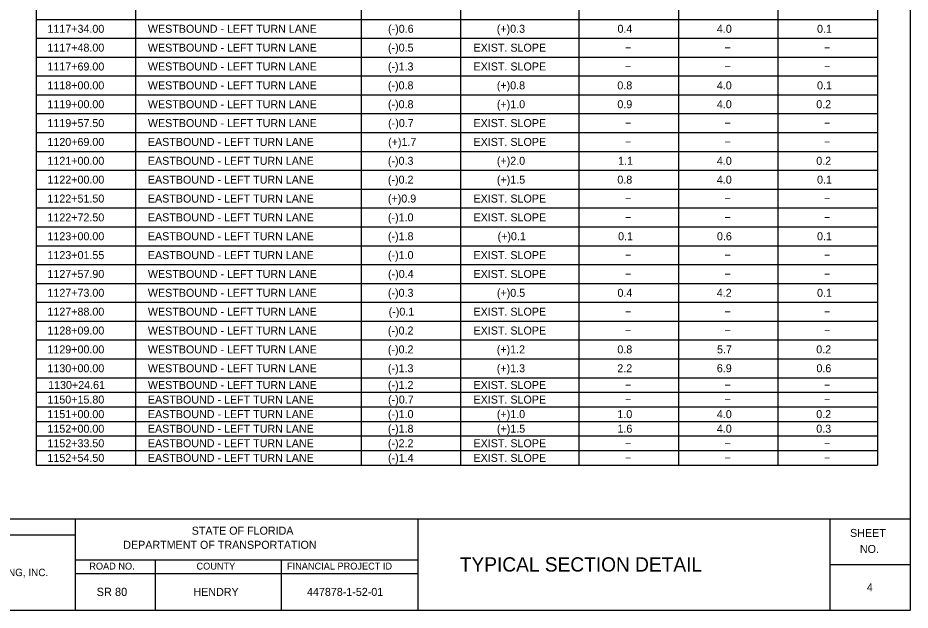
# Model space of a CAD drawing. Extents: x 0.03 to 1.66, y 0 to 0.87.
# Drawn here: x 0.679 to 1.329, y 0.004 to 0.436 of the extents above; entities that cross this region are included whole.
import ezdxf

# ---------------------------------------------------------------- set-up
doc = ezdxf.new("R2010")
doc.units = 0
for name, color, linetype in [('SheetBorder_dp', 7, 'Continuous'), ('SheetLines_dp', 7, 'Continuous'), ('SumBoxBorder_dp', 7, 'Continuous'), ('SumBoxLines_dp', 7, 'Continuous'), ('SumBoxLinesMin_dp', 7, 'Continuous'), ('TextLabel', 7, 'Continuous'), ('TextMisc', 7, 'Continuous'), ('TextShtNo', 7, 'Continuous')]:
    doc.layers.add(name, color=color, linetype=linetype)

msp = doc.modelspace()

# ---------------------------------------------------------------- linework, layer by layer
at = {"layer": 'SheetBorder_dp'}
for p, q in [((1.32916, 0.87083), (1.32916, 0.00417)), ((0.04583, 0.07083), (1.32916, 0.07083)), ((0.04583, 0.00417), (1.32916, 0.00417))]:
    msp.add_line(p, q, dxfattribs=at)
at = {"layer": 'SheetLines_dp'}
for p, q in [((0.72083, 0.07083), (0.72083, 0.00417)), ((0.97083, 0.00417), (0.97083, 0.07083)), ((1.27083, 0.00417), (1.27083, 0.07083)), ((0.52621, 0.05917), (0.72084, 0.05917)), ((0.72083, 0.04083), (0.97083, 0.04083)), ((0.77916, 0.04083), (0.77916, 0.00417)), ((0.87083, 0.04083), (0.87083, 0.00417)), ((1.27083, 0.0375), (1.32916, 0.0375)), ((0.72083, 0.03083), (0.97083, 0.03083))]:
    msp.add_line(p, q, dxfattribs=at)
at = {"layer": 'SumBoxBorder_dp'}
msp.add_line((1.30527, 0.82332), (1.30527, 0.10985), dxfattribs=at)
msp.add_line((1.30527, 0.82332), (1.30527, 0.10985), dxfattribs=at)
at = {"layer": 'SumBoxLines_dp'}
for p, q in [((0.69239, 0.82332), (0.69239, 0.10985)), ((0.92917, 0.80332), (0.92917, 0.10985)), ((0.92917, 0.80332), (0.92917, 0.10985)), ((1.00164, 0.80332), (1.00164, 0.10985)), ((1.00164, 0.80332), (1.00164, 0.10985)), ((1.08785, 0.80332), (1.08785, 0.10985)), ((1.08785, 0.80332), (1.08785, 0.10985)), ((1.16032, 0.80332), (1.16032, 0.10985)), ((1.16032, 0.80332), (1.16032, 0.10985)), ((1.23279, 0.80332), (1.23279, 0.10985)), ((1.23279, 0.80332), (1.23279, 0.10985)), ((0.76486, 0.78333), (0.76486, 0.10985)), ((0.76486, 0.78333), (0.76486, 0.10985))]:
    msp.add_line(p, q, dxfattribs=at)
at = {"layer": 'SumBoxLinesMin_dp'}
for p, q in [((0.69239, 0.43472), (1.30527, 0.43472)), ((0.69239, 0.43472), (1.30527, 0.43472)), ((0.69239, 0.42098), (1.30527, 0.42098)), ((0.69239, 0.42098), (1.30527, 0.42098)), ((0.69239, 0.40723), (1.30527, 0.40723)), ((0.69239, 0.40723), (1.30527, 0.40723)), ((0.69239, 0.39349), (1.30527, 0.39349)), ((0.69239, 0.39349), (1.30527, 0.39349)), ((0.69239, 0.37974), (1.30527, 0.37974)), ((0.69239, 0.37974), (1.30527, 0.37974)), ((0.69239, 0.366), (1.30527, 0.366)), ((0.69239, 0.366), (1.30527, 0.366)), ((0.69239, 0.35225), (1.30527, 0.35225)), ((0.69239, 0.35225), (1.30527, 0.35225)), ((0.69239, 0.33851), (1.30527, 0.33851)), ((0.69239, 0.33851), (1.30527, 0.33851)), ((0.69239, 0.32477), (1.30527, 0.32477)), ((0.69239, 0.32477), (1.30527, 0.32477)), ((0.69239, 0.31102), (1.30527, 0.31102)), ((0.69239, 0.31102), (1.30527, 0.31102)), ((0.69239, 0.29728), (1.30527, 0.29728)), ((0.69239, 0.29728), (1.30527, 0.29728)), ((0.69239, 0.28353), (1.30527, 0.28353)), ((0.69239, 0.28353), (1.30527, 0.28353)), ((0.69239, 0.26979), (1.30527, 0.26979)), ((0.69239, 0.26979), (1.30527, 0.26979)), ((0.69239, 0.25604), (1.30527, 0.25604)), ((0.69239, 0.25604), (1.30527, 0.25604)), ((0.69239, 0.2423), (1.30527, 0.2423)), ((0.69239, 0.2423), (1.30527, 0.2423)), ((0.69239, 0.22855), (1.30527, 0.22855)), ((0.69239, 0.22855), (1.30527, 0.22855)), ((0.69239, 0.21481), (1.30527, 0.21481)), ((0.69239, 0.21481), (1.30527, 0.21481)), ((0.69239, 0.20107), (1.30527, 0.20107)), ((0.69239, 0.20107), (1.30527, 0.20107)), ((0.69239, 0.18732), (1.30527, 0.18732)), ((0.69239, 0.18732), (1.30527, 0.18732)), ((0.69239, 0.17358), (1.30527, 0.17358)), ((0.69239, 0.17358), (1.30527, 0.17358)), ((0.69239, 0.16296), (1.30527, 0.16296)), ((0.69239, 0.16296), (1.30527, 0.16296)), ((0.69239, 0.15233), (1.30527, 0.15233)), ((0.69239, 0.15233), (1.30527, 0.15233)), ((0.69239, 0.14171), (1.30527, 0.14171)), ((0.69239, 0.14171), (1.30527, 0.14171)), ((0.69239, 0.13109), (1.30527, 0.13109)), ((0.69239, 0.13109), (1.30527, 0.13109)), ((0.69239, 0.12047), (1.30527, 0.12047)), ((0.69239, 0.12047), (1.30527, 0.12047)), ((0.69239, 0.10985), (1.30527, 0.10985))]:
    msp.add_line(p, q, dxfattribs=at)

# ---------------------------------------------------------------- texts
at = {"layer": 'TextLabel'}
for s, height, p in [('1117+34.00', 0.005831, (0.70065, 0.42493)), ('WESTBOUND - LEFT TURN LANE', 0.005831, (0.77383, 0.42493)), ('(-)0.6', 0.005831, (0.94879, 0.42493)), ('(+)0.3', 0.005831, (1.02802, 0.42493)), ('0.4', 0.005831, (1.11594, 0.42493)), ('4.0', 0.005831, (1.18835, 0.42493)), ('0.1', 0.005831, (1.26133, 0.42493)), ('1117+48.00', 0.005831, (0.70065, 0.41119)), ('WESTBOUND - LEFT TURN LANE', 0.005831, (0.77383, 0.41119)), ('(-)0.5', 0.005831, (0.94875, 0.41119)), ('EXIST. SLOPE', 0.005831, (1.01107, 0.41119)), ('−', 0.00583, (1.12147, 0.41119)), ('−', 0.00583, (1.19394, 0.41119)), ('−', 0.00583, (1.26641, 0.41119)), ('1117+69.00', 0.005831, (0.70065, 0.39745)), ('WESTBOUND - LEFT TURN LANE', 0.005831, (0.77383, 0.39745)), ('(-)1.3', 0.005831, (0.94867, 0.39745)), ('EXIST. SLOPE', 0.005831, (1.01107, 0.39745)), ('−', 0.00583, (1.12147, 0.39745)), ('−', 0.00583, (1.19394, 0.39745)), ('−', 0.00583, (1.26641, 0.39745)), ('1118+00.00', 0.005831, (0.70065, 0.3837)), ('WESTBOUND - LEFT TURN LANE', 0.005831, (0.77383, 0.3837)), ('(-)0.8', 0.005831, (0.9487, 0.3837)), ('(+)0.8', 0.005831, (1.02804, 0.3837)), ('0.8', 0.005831, (1.11585, 0.3837)), ('4.0', 0.005831, (1.18835, 0.3837)), ('0.1', 0.005831, (1.26133, 0.3837)), ('1119+00.00', 0.005831, (0.70065, 0.36996)), ('WESTBOUND - LEFT TURN LANE', 0.005831, (0.77383, 0.36996)), ('(-)0.8', 0.005831, (0.9487, 0.36996)), ('(+)1.0', 0.005831, (1.02807, 0.36996)), ('0.9', 0.005831, (1.11586, 0.36996)), ('4.0', 0.005831, (1.18835, 0.36996)), ('0.2', 0.005831, (1.26077, 0.36996)), ('1119+57.50', 0.005831, (0.70065, 0.35621)), ('WESTBOUND - LEFT TURN LANE', 0.005831, (0.77383, 0.35621)), ('(-)0.7', 0.005831, (0.94884, 0.35621)), ('EXIST. SLOPE', 0.005831, (1.01107, 0.35621)), ('−', 0.00583, (1.12147, 0.35621)), ('−', 0.00583, (1.19394, 0.35621)), ('−', 0.00583, (1.26641, 0.35621)), ('1120+69.00', 0.005831, (0.70065, 0.34247)), ('EASTBOUND - LEFT TURN LANE', 0.005831, (0.77383, 0.34247)), ('(+)1.7', 0.005831, (0.94884, 0.34247)), ('EXIST. SLOPE', 0.005831, (1.01107, 0.34247)), ('−', 0.00583, (1.12147, 0.34247)), ('−', 0.00583, (1.19394, 0.34247)), ('−', 0.00583, (1.26641, 0.34247)), ('1121+00.00', 0.005831, (0.70065, 0.32872)), ('EASTBOUND - LEFT TURN LANE', 0.005831, (0.77383, 0.32872)), ('(-)0.3', 0.005831, (0.94867, 0.32872)), ('(+)2.0', 0.005831, (1.02807, 0.32872)), ('1.1', 0.005831, (1.11639, 0.32872)), ('4.0', 0.005831, (1.18835, 0.32872)), ('0.2', 0.005831, (1.26077, 0.32872)), ('1122+00.00', 0.005831, (0.70065, 0.31498)), ('EASTBOUND - LEFT TURN LANE', 0.005831, (0.77383, 0.31498)), ('(-)0.2', 0.005831, (0.94868, 0.31498)), ('(+)1.5', 0.005831, (1.02809, 0.31498)), ('0.8', 0.005831, (1.11585, 0.31498)), ('4.0', 0.005831, (1.18835, 0.31498)), ('0.1', 0.005831, (1.26133, 0.31498)), ('1122+51.50', 0.005831, (0.70065, 0.30123)), ('EASTBOUND - LEFT TURN LANE', 0.005831, (0.77383, 0.30123)), ('(+)0.9', 0.005831, (0.94871, 0.30123)), ('EXIST. SLOPE', 0.005831, (1.01107, 0.30123)), ('−', 0.00583, (1.12147, 0.30123)), ('−', 0.00583, (1.19394, 0.30123)), ('−', 0.00583, (1.26641, 0.30123)), ('1122+72.50', 0.005831, (0.70065, 0.28749)), ('EASTBOUND - LEFT TURN LANE', 0.005831, (0.77383, 0.28749)), ('(-)1.0', 0.005831, (0.94872, 0.28749)), ('EXIST. SLOPE', 0.005831, (1.01107, 0.28749)), ('−', 0.00583, (1.12147, 0.28749)), ('−', 0.00583, (1.19394, 0.28749)), ('−', 0.00583, (1.26641, 0.28749)), ('1123+00.00', 0.005831, (0.70065, 0.27374)), ('EASTBOUND - LEFT TURN LANE', 0.005831, (0.77383, 0.27374)), ('(-)1.8', 0.005831, (0.9487, 0.27374)), ('(+)0.1', 0.005831, (1.02858, 0.27374)), ('0.1', 0.005831, (1.11639, 0.27374)), ('0.6', 0.005831, (1.18841, 0.27374)), ('0.1', 0.005831, (1.26133, 0.27374)), ('1123+01.55', 0.005831, (0.70068, 0.26)), ('EASTBOUND - LEFT TURN LANE', 0.005831, (0.77383, 0.26)), ('(-)1.0', 0.005831, (0.94872, 0.26)), ('EXIST. SLOPE', 0.005831, (1.01107, 0.26)), ('−', 0.00583, (1.12147, 0.26)), ('−', 0.00583, (1.19394, 0.26)), ('−', 0.00583, (1.26641, 0.26)), ('1127+57.90', 0.005831, (0.70065, 0.24626)), ('WESTBOUND - LEFT TURN LANE', 0.005831, (0.77383, 0.24626)), ('(-)0.4', 0.005831, (0.94879, 0.24626)), ('EXIST. SLOPE', 0.005831, (1.01107, 0.24626)), ('−', 0.00583, (1.12147, 0.24626)), ('−', 0.00583, (1.19394, 0.24626)), ('−', 0.00583, (1.26641, 0.24626)), ('1127+73.00', 0.005831, (0.70065, 0.23251)), ('WESTBOUND - LEFT TURN LANE', 0.005831, (0.77383, 0.23251)), ('(-)0.3', 0.005831, (0.94867, 0.23251)), ('(+)0.5', 0.005831, (1.02809, 0.23251)), ('0.4', 0.005831, (1.11594, 0.23251)), ('4.2', 0.005831, (1.1883, 0.23251)), ('0.1', 0.005831, (1.26133, 0.23251)), ('1127+88.00', 0.005831, (0.70065, 0.21877)), ('WESTBOUND - LEFT TURN LANE', 0.005831, (0.77383, 0.21877)), ('(-)0.1', 0.005831, (0.94924, 0.21877)), ('EXIST. SLOPE', 0.005831, (1.01107, 0.21877)), ('−', 0.00583, (1.12147, 0.21877)), ('−', 0.00583, (1.19394, 0.21877)), ('−', 0.00583, (1.26641, 0.21877)), ('1128+09.00', 0.005831, (0.70065, 0.20502)), ('WESTBOUND - LEFT TURN LANE', 0.005831, (0.77383, 0.20502)), ('(-)0.2', 0.005831, (0.94868, 0.20502)), ('EXIST. SLOPE', 0.005831, (1.01107, 0.20502)), ('−', 0.00583, (1.12147, 0.20502)), ('−', 0.00583, (1.19394, 0.20502)), ('−', 0.00583, (1.26641, 0.20502)), ('1129+00.00', 0.005831, (0.70065, 0.19128)), ('WESTBOUND - LEFT TURN LANE', 0.005831, (0.77383, 0.19128)), ('(-)0.2', 0.005831, (0.94868, 0.19128)), ('(+)1.2', 0.005831, (1.02802, 0.19128)), ('0.8', 0.005831, (1.11585, 0.19128)), ('5.7', 0.005831, (1.18847, 0.19128)), ('0.2', 0.005831, (1.26077, 0.19128)), ('1130+00.00', 0.005831, (0.70065, 0.17753)), ('WESTBOUND - LEFT TURN LANE', 0.005831, (0.77383, 0.17753)), ('(-)1.3', 0.005831, (0.94867, 0.17753)), ('(+)1.3', 0.005831, (1.02802, 0.17753)), ('2.2', 0.005831, (1.11583, 0.17753)), ('6.9', 0.005831, (1.18833, 0.17753)), ('0.6', 0.005831, (1.26089, 0.17753)), ('1130+24.61', 0.005831, (0.70117, 0.16535)), ('WESTBOUND - LEFT TURN LANE', 0.005831, (0.77383, 0.16535)), ('(-)1.2', 0.005831, (0.94868, 0.16535)), ('EXIST. SLOPE', 0.005831, (1.01107, 0.16535)), ('−', 0.00583, (1.12147, 0.16535)), ('−', 0.00583, (1.19394, 0.16535)), ('−', 0.00583, (1.26641, 0.16535)), ('1150+15.80', 0.005831, (0.70065, 0.15473)), ('EASTBOUND - LEFT TURN LANE', 0.005831, (0.77383, 0.15473)), ('(-)0.7', 0.005831, (0.94884, 0.15473)), ('EXIST. SLOPE', 0.005831, (1.01107, 0.15473)), ('−', 0.00583, (1.12147, 0.15473)), ('−', 0.00583, (1.19394, 0.15473)), ('−', 0.00583, (1.26641, 0.15473)), ('1151+00.00', 0.005831, (0.70065, 0.14411)), ('EASTBOUND - LEFT TURN LANE', 0.005831, (0.77383, 0.14411)), ('(-)1.0', 0.005831, (0.94872, 0.14411)), ('(+)1.0', 0.005831, (1.02807, 0.14411)), ('1.0', 0.005831, (1.11588, 0.14411)), ('4.0', 0.005831, (1.18835, 0.14411)), ('0.2', 0.005831, (1.26077, 0.14411)), ('1152+00.00', 0.005831, (0.70065, 0.13349)), ('EASTBOUND - LEFT TURN LANE', 0.005831, (0.77383, 0.13349)), ('(-)1.8', 0.005831, (0.9487, 0.13349)), ('(+)1.5', 0.005831, (1.02809, 0.13349)), ('1.6', 0.005831, (1.11594, 0.13349)), ('4.0', 0.005831, (1.18835, 0.13349)), ('0.3', 0.005831, (1.26077, 0.13349)), ('1152+33.50', 0.005831, (0.70065, 0.12287)), ('EASTBOUND - LEFT TURN LANE', 0.005831, (0.77383, 0.12287)), ('(-)2.2', 0.005831, (0.94868, 0.12287)), ('EXIST. SLOPE', 0.005831, (1.01107, 0.12287)), ('−', 0.00583, (1.12147, 0.12287)), ('−', 0.00583, (1.19394, 0.12287)), ('−', 0.00583, (1.26641, 0.12287)), ('1152+54.50', 0.005831, (0.70065, 0.11225)), ('EASTBOUND - LEFT TURN LANE', 0.005831, (0.77383, 0.11225)), ('(-)1.4', 0.005831, (0.94879, 0.11225)), ('EXIST. SLOPE', 0.005831, (1.01107, 0.11225)), ('−', 0.00583, (1.12147, 0.11225)), ('−', 0.00583, (1.19394, 0.11225)), ('−', 0.00583, (1.26641, 0.11225))]:
    msp.add_text(s, height=height, dxfattribs=at).set_placement(p)
at = {"layer": 'TextMisc'}
for s, height, p in [('STATE OF FLORIDA', 0.0058333, (0.80578, 0.05918)), ('DEPARTMENT OF TRANSPORTATION', 0.0058333, (0.75589, 0.04888)), ('TYPICAL SECTION DETAIL', 0.0104166, (1.00108, 0.03229)), ('FLORIDA TRANSPORTATION ENGINEERING, INC.', 0.0054, (0.5303, 0.02897)), ('ROAD NO.', 0.005, (0.73115, 0.03376)), ('COUNTY', 0.005, (0.80925, 0.03376)), ('FINANCIAL PROJECT ID', 0.005, (0.87518, 0.03376)), ('SR 80', 0.006, (0.73648, 0.0145)), ('HENDRY', 0.005833, (0.80701, 0.01458)), ('447878-1-52-01', 0.0058331, (0.88977, 0.01458))]:
    msp.add_text(s, height=height, dxfattribs=at).set_placement(p)
for s, p in [('SHEET', (1.2854, 0.05754)), ('NO.', (1.29254, 0.04586))]:
    msp.add_text(s, height=0.005833, rotation=359.86066, dxfattribs=at).set_placement(p)
at = {"layer": 'TextShtNo'}
msp.add_text('4', height=0.00583, dxfattribs=at).set_placement((1.29762, 0.01792))

doc.saveas('drawing.dxf')
